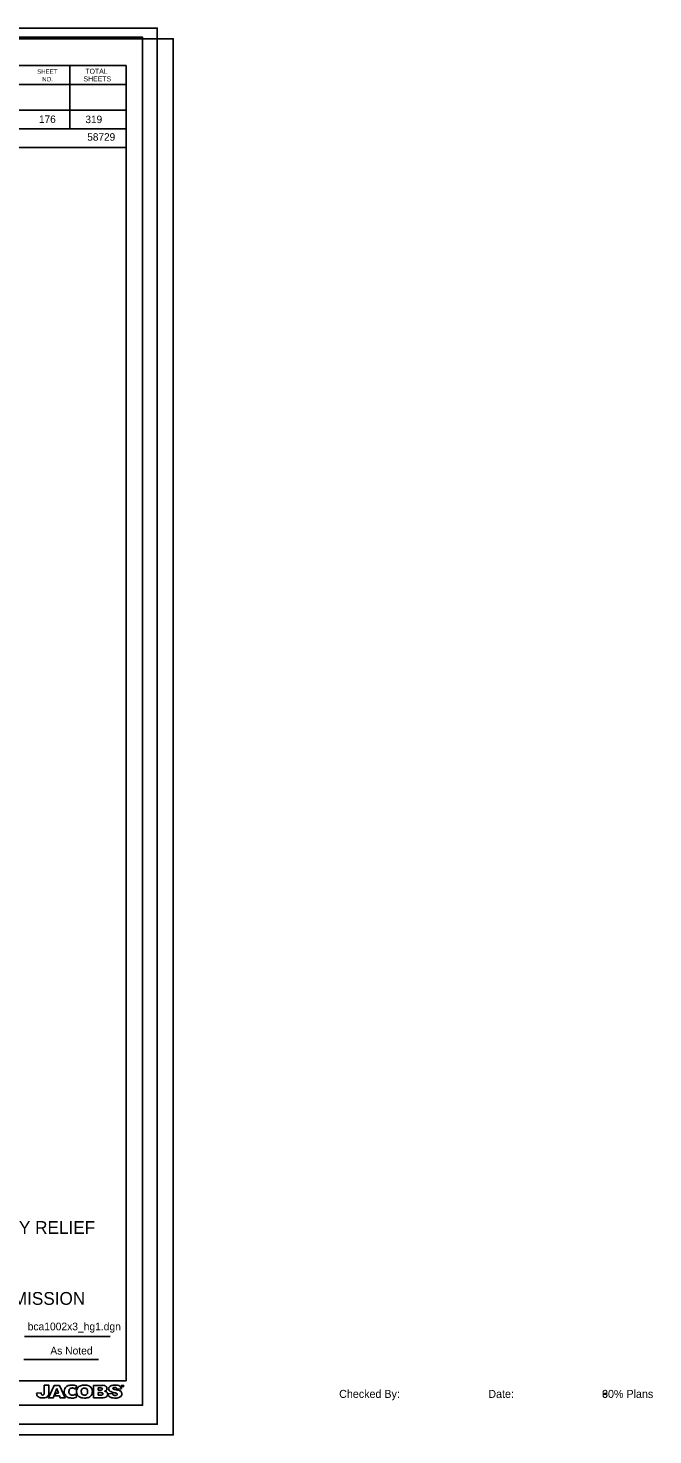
# Model space of a CAD drawing. Extents: x -1063117.9 to -1063075.9, y -253323.6 to -253301.6.
# Drawn here: x -1063085.67 to -1063075.92, y -253323.61 to -253301.63 of the extents above; entities that cross this region are included whole.
import ezdxf

# ---------------------------------------------------------------- set-up
doc = ezdxf.new("R2010")
doc.units = 0
for name, color, linetype in [('30% Plans', 7, 'Continuous'), ('60% Plans', 7, 'Continuous'), ('90% Plans', 7, 'Continuous'), ('border', 7, 'Continuous'), ('Border 2660-Hwy18 - Level 62', 7, 'Continuous'), ('Border 2660-Hwy18 - Level 63', 7, 'Continuous'), ('Border 2660-Hwy18 - Text', 7, 'Continuous'), ('Border 2660-Hwy18 - Title Text', 7, 'Continuous'), ('Level 62 PDF', 7, 'Continuous'), ('Text', 7, 'Continuous'), ('Title Block Text', 7, 'Continuous'), ('Title Text', 7, 'Continuous')]:
    doc.layers.add(name, color=color, linetype=linetype)

msp = doc.modelspace()

# ---------------------------------------------------------------- linework, layer by layer
at = {"layer": 'border'}
for p, q in [((-1063116.157, -253302.216), (-1063084.146, -253302.216)), ((-1063085.026, -253302.216), (-1063085.026, -253303.204)), ((-1063084.146, -253322.761), (-1063084.146, -253302.216)), ((-1063084.146, -253302.51), (-1063088.456, -253302.51)), ((-1063084.146, -253302.508), (-1063084.146, -253302.508)), ((-1063084.146, -253302.91), (-1063088.456, -253302.91)), ((-1063088.16, -253302.91), (-1063084.146, -253302.91)), ((-1063084.146, -253303.204), (-1063092.372, -253303.204)), ((-1063088.456, -253303.495), (-1063084.146, -253303.495)), ((-1063085.73, -253322.071), (-1063084.394, -253322.071)), ((-1063085.742, -253322.431), (-1063084.577, -253322.431)), ((-1063084.146, -253322.761), (-1063116.157, -253322.761))]:
    msp.add_line(p, q, dxfattribs=at)
for points in [[(-1063085.351, -253322.941), (-1063085.351, -253322.831), (-1063085.425, -253322.831), (-1063085.425, -253322.951)], [(-1063085.228, -253322.883), (-1063085.202, -253322.954), (-1063085.241, -253322.954), (-1063085.257, -253322.996), (-1063085.187, -253322.996), (-1063085.175, -253323.029), (-1063085.098, -253323.029), (-1063085.187, -253322.833), (-1063085.268, -253322.833), (-1063085.358, -253323.029), (-1063085.282, -253323.029), (-1063085.228, -253322.883)], [(-1063084.512, -253322.833), (-1063084.654, -253322.833), (-1063084.654, -253323.029)], [(-1063084.547, -253322.872), (-1063084.58, -253322.872), (-1063084.58, -253322.909)], [(-1063084.207, -253322.835), (-1063084.222, -253322.835), (-1063084.222, -253322.837), (-1063084.216, -253322.837), (-1063084.216, -253322.854), (-1063084.214, -253322.854), (-1063084.214, -253322.837), (-1063084.207, -253322.837), (-1063084.207, -253322.835)], [(-1063084.203, -253322.838), (-1063084.203, -253322.838), (-1063084.197, -253322.854), (-1063084.195, -253322.854), (-1063084.189, -253322.838), (-1063084.189, -253322.838), (-1063084.189, -253322.854), (-1063084.186, -253322.854), (-1063084.186, -253322.835), (-1063084.19, -253322.835), (-1063084.196, -253322.851), (-1063084.202, -253322.835), (-1063084.205, -253322.835), (-1063084.205, -253322.854), (-1063084.203, -253322.854), (-1063084.203, -253322.838)], [(-1063085.473, -253322.952), (-1063085.543, -253322.956)], [(-1063084.654, -253323.029), (-1063084.526, -253323.029)], [(-1063084.58, -253322.909), (-1063084.545, -253322.909)], [(-1063084.542, -253322.947), (-1063084.58, -253322.947), (-1063084.58, -253322.987)], [(-1063084.58, -253322.987), (-1063084.542, -253322.987)], [(-1063084.358, -253322.96), (-1063084.428, -253322.964)], [(-1063084.289, -253322.891), (-1063084.219, -253322.888)]]:
    msp.add_lwpolyline(points, dxfattribs=at)
for centre, radius, start, end in [((-1063085.013, -253322.926), 0.0987, 155.2444, 178.6811), ((-1063085.029, -253322.918), 0.0809, 126.8513, 155.2444), ((-1063085.009, -253322.944), 0.114, 94.7853, 126.8513), ((-1063084.988, -253322.93), 0.0556, 110.7655, 134.3139), ((-1063084.989, -253323.193), 0.363, 86.903, 94.7853), ((-1063084.989, -253322.928), 0.0529, 91.5073, 110.7655), ((-1063084.987, -253322.99), 0.116, 82.6359, 91.5073), ((-1063084.979, -253322.924), 0.0493, 65.5548, 82.6359), ((-1063084.975, -253322.943), 0.113, 56.9246, 86.903), ((-1063085.007, -253322.988), 0.119, 54.6002, 65.5548), ((-1063084.689, -253323.008), 0.276, 144.635, 154.8844), ((-1063084.82, -253322.928), 0.1, 148.6249, 181.2859), ((-1063084.841, -253322.915), 0.0755, 123.8806, 148.6249), ((-1063084.804, -253322.971), 0.142, 111.7104, 123.8806), ((-1063084.816, -253322.94), 0.109, 96.5371, 111.7104), ((-1063084.798, -253322.926), 0.0518, 117.7176, 136.1177), ((-1063084.785, -253323.213), 0.384, 91.9058, 96.5371), ((-1063084.804, -253322.914), 0.0382, 100.2108, 117.7176), ((-1063084.795, -253322.965), 0.0895, 90.9675, 100.2108), ((-1063084.791, -253322.995), 0.166, 73.4477, 92.4253), ((-1063084.796, -253322.937), 0.0622, 67.077, 90.4218), ((-1063084.787, -253322.916), 0.0386, 24.6274, 67.077), ((-1063084.775, -253322.943), 0.112, 41.1934, 73.4477), ((-1063084.735, -253322.908), 0.0579, 18.6966, 41.1934), ((-1063084.549, -253323.007), 0.135, 86.2098, 89.3498), ((-1063084.543, -253322.924), 0.0514, 74.8723, 86.2098), ((-1063084.535, -253322.893), 0.0196, 40.2425, 74.8723), ((-1063084.528, -253322.887), 0.0108, 21.9604, 40.2425), ((-1063084.536, -253322.891), 0.0195, 341.4625, 21.9604), ((-1063084.512, -253322.936), 0.104, 72.1885, 90.1477), ((-1063084.499, -253322.895), 0.0603, 61.4844, 72.1885), ((-1063084.497, -253322.892), 0.0564, 34.7868, 61.4844), ((-1063084.476, -253322.877), 0.0315, 16.9455, 34.7868), ((-1063084.49, -253322.881), 0.0455, 347.0949, 16.9455), ((-1063084.372, -253322.888), 0.0476, 124.08, 177.6485), ((-1063084.378, -253322.887), 0.0416, 177.6485, 218.8535), ((-1063084.341, -253322.934), 0.103, 108.2808, 124.08), ((-1063084.347, -253322.913), 0.0811, 99.8173, 108.2808), ((-1063084.32, -253323.072), 0.242, 93.402, 99.8173), ((-1063084.335, -253322.883), 0.016, 146.4706, 165.3108), ((-1063084.343, -253322.881), 0.00815, 165.3108, 208.2887), ((-1063084.336, -253322.876), 0.0169, 211.7417, 226.6339), ((-1063084.341, -253322.879), 0.00877, 130.7855, 146.4706), ((-1063084.331, -253322.892), 0.0256, 97.3055, 130.7855), ((-1063084.319, -253323.083), 0.254, 80.6549, 93.402), ((-1063084.325, -253322.935), 0.0692, 81.3212, 97.3055), ((-1063084.32, -253322.902), 0.0359, 57.474, 81.3212), ((-1063084.312, -253322.889), 0.0202, 37.1977, 57.474), ((-1063084.323, -253322.898), 0.0351, 11.0051, 37.1977), ((-1063084.293, -253322.921), 0.0897, 57.5906, 80.6549), ((-1063084.271, -253322.887), 0.0494, 39.0736, 57.5906), ((-1063084.28, -253322.895), 0.0612, 6.4385, 39.0736), ((-1063085.421, -253322.946), 0.123, 184.5698, 198.1069), ((-1063085.488, -253322.968), 0.0527, 198.1069, 225.9799), ((-1063085.469, -253322.949), 0.0797, 225.9799, 261.0714), ((-1063085.444, -253322.786), 0.244, 261.0714, 269.9405), ((-1063085.412, -253322.954), 0.0602, 178.2556, 191.4961), ((-1063085.444, -253322.961), 0.0277, 191.4961, 218.7511), ((-1063085.453, -253322.968), 0.0164, 218.7511, 257.488), ((-1063085.449, -253322.95), 0.0345, 257.488, 275.7834), ((-1063085.448, -253322.959), 0.0257, 275.7834, 301.6926), ((-1063085.444, -253322.863), 0.167, 269.9405, 279.1616), ((-1063085.441, -253322.97), 0.0122, 301.6926, 325.4171), ((-1063085.455, -253322.961), 0.0285, 325.4171, 349.1575), ((-1063085.504, -253322.952), 0.0792, 349.1575, 360), ((-1063085.432, -253322.936), 0.0931, 279.1616, 305.8646), ((-1063085.412, -253322.964), 0.0585, 305.8646, 338.7843), ((-1063085.406, -253322.966), 0.0527, 338.7843, 350.0951), ((-1063085.895, -253322.881), 0.549, 350.0951, 351.3706), ((-1063085.475, -253322.945), 0.124, 351.3706, 1.8291), ((-1063084.959, -253322.927), 0.153, 178.6811, 194.3912), ((-1063085.05, -253322.95), 0.0582, 194.3912, 214.1799), ((-1063084.994, -253322.912), 0.127, 214.1799, 231.6615), ((-1063085.025, -253322.951), 0.0765, 231.6616, 258.686), ((-1063084.981, -253322.734), 0.298, 258.686, 268.8163), ((-1063084.934, -253322.933), 0.104, 161.2834, 178.6702), ((-1063084.953, -253322.933), 0.0855, 178.6702, 195.8531), ((-1063084.994, -253322.945), 0.0421, 195.8531, 214.5369), ((-1063085.01, -253322.908), 0.0243, 134.3139, 161.2834), ((-1063084.997, -253322.946), 0.0388, 214.5369, 253.1918), ((-1063084.986, -253322.91), 0.0769, 253.1918, 291.1956), ((-1063084.985, -253322.886), 0.146, 268.8163, 299.3878), ((-1063084.992, -253322.895), 0.0928, 291.1956, 305.5144), ((-1063084.575, -253322.788), 0.407, 206.7197, 213.678), ((-1063084.768, -253322.927), 0.152, 181.2859, 193.1956), ((-1063084.85, -253322.946), 0.0683, 193.1956, 217.7499), ((-1063084.816, -253322.92), 0.111, 217.7499, 244.1703), ((-1063084.827, -253322.943), 0.0859, 244.1703, 259.4942), ((-1063084.755, -253322.931), 0.0917, 160.8611, 181.2981), ((-1063084.751, -253322.931), 0.0951, 181.2981, 197.9492), ((-1063084.788, -253322.733), 0.299, 259.4942, 268.6426), ((-1063084.814, -253322.91), 0.0287, 136.1177, 160.8611), ((-1063084.814, -253322.951), 0.0299, 197.9492, 222.7741), ((-1063084.801, -253322.939), 0.0474, 222.7741, 250.1955), ((-1063084.8, -253322.936), 0.0507, 250.1955, 269.1264), ((-1063084.797, -253322.795), 0.191, 269.1264, 272.0424), ((-1063084.791, -253322.852), 0.18, 268.6426, 285.9017), ((-1063084.792, -253322.935), 0.0512, 272.0424, 299.5401), ((-1063084.785, -253322.949), 0.036, 299.5401, 342.4003), ((-1063084.803, -253322.923), 0.056, 2.7442, 24.6274), ((-1063084.837, -253322.932), 0.091, 342.4003, 0.0845), ((-1063084.996, -253322.932), 0.249, 0.0845, 2.7442), ((-1063084.769, -253322.929), 0.101, 285.9017, 322.6714), ((-1063084.745, -253322.947), 0.0698, 322.6714, 344.5708), ((-1063084.803, -253322.931), 0.13, 344.5708, 18.6966), ((-1063084.545, -253322.846), 0.0633, 270.0363, 284.1438), ((-1063084.547, -253323.194), 0.247, 86.6838, 88.8756), ((-1063084.542, -253322.883), 0.104, 270.0001, 276.6749), ((-1063084.536, -253322.997), 0.0497, 75.9314, 86.6838), ((-1063084.535, -253322.888), 0.0196, 284.1438, 307.8865), ((-1063084.535, -253322.943), 0.043, 276.6749, 293.0645), ((-1063084.537, -253322.691), 0.338, 271.7224, 279.6279), ((-1063084.532, -253322.892), 0.0149, 307.8866, 341.4625), ((-1063084.531, -253322.98), 0.0328, 59.6202, 75.9314), ((-1063084.525, -253322.966), 0.0178, 293.0645, 337.5037), ((-1063084.522, -253322.965), 0.015, 30.8341, 59.6202), ((-1063084.525, -253322.966), 0.0177, 337.5037, 30.8341), ((-1063084.502, -253322.851), 0.0753, 284.6785, 296.8411), ((-1063084.499, -253323.015), 0.092, 61.0815, 79.9242), ((-1063084.49, -253322.964), 0.0609, 279.6279, 313.6357), ((-1063084.489, -253322.877), 0.0471, 296.8412, 329.8182), ((-1063084.474, -253322.968), 0.039, 44.9773, 61.0815), ((-1063084.475, -253322.885), 0.0307, 329.8182, 347.0949), ((-1063084.484, -253322.971), 0.0511, 313.6357, 342.9845), ((-1063084.478, -253322.973), 0.0452, 342.9845, 44.9773), ((-1063084.052, -253322.911), 0.38, 187.9971, 189.0947), ((-1063084.378, -253322.963), 0.0503, 189.0947, 202.464), ((-1063084.343, -253322.949), 0.0881, 202.464, 215.8926), ((-1063084.364, -253322.964), 0.0621, 215.8926, 243.2968), ((-1063084.366, -253322.878), 0.0566, 218.8535, 233.6549), ((-1063084.352, -253322.859), 0.0797, 233.6549, 244.7689), ((-1063084.351, -253322.939), 0.0904, 243.2968, 257.4598), ((-1063084.32, -253322.79), 0.156, 244.7689, 253.473), ((-1063084.324, -253322.819), 0.213, 257.4598, 268.8656), ((-1063084.272, -253322.63), 0.323, 253.473, 259.8297), ((-1063084.306, -253322.952), 0.0523, 188.5141, 201.638), ((-1063084.325, -253322.96), 0.0319, 201.638, 242.3635), ((-1063084.338, -253322.878), 0.0145, 226.6339, 245.1429), ((-1063084.321, -253322.841), 0.0549, 245.1429, 260.9806), ((-1063084.319, -253322.948), 0.045, 242.3635, 264.6229), ((-1063084.404, -253323.369), 0.479, 77.5139, 80.9806), ((-1063084.382, -253323.24), 0.297, 76.0104, 79.8297), ((-1063084.317, -253322.451), 0.581, 268.8656, 270.7612), ((-1063084.316, -253322.913), 0.0806, 264.6229, 273.901), ((-1063084.334, -253323.047), 0.0974, 67.9593, 76.0104), ((-1063084.314, -253322.947), 0.0464, 273.901, 289.1925), ((-1063084.312, -253322.855), 0.177, 270.7612, 282.5001), ((-1063084.728, -253324.831), 1.977, 76.8035, 77.5139), ((-1063084.307, -253322.966), 0.0263, 289.1925, 322.566), ((-1063084.307, -253322.981), 0.0265, 39.9313, 67.9593), ((-1063084.298, -253322.973), 0.0145, 2.1813, 39.9313), ((-1063084.297, -253322.973), 0.0141, 322.566, 2.1813), ((-1063084.314, -253323.065), 0.163, 65.6998, 76.8035), ((-1063084.297, -253322.921), 0.109, 282.5001, 295.6144), ((-1063084.283, -253322.95), 0.0772, 295.6144, 314.022), ((-1063084.279, -253322.987), 0.0776, 51.3565, 65.6998), ((-1063084.263, -253322.967), 0.0523, 36.5162, 51.3565), ((-1063084.272, -253322.962), 0.0608, 314.022, 345.1611), ((-1063084.26, -253322.965), 0.0486, 345.1611, 36.5162)]:
    msp.add_arc(centre, radius, start, end, dxfattribs=at)
at = {"layer": 'Border 2660-Hwy18 - Level 62'}
msp.add_lwpolyline([(-1063117.777, -253301.63), (-1063083.659, -253301.63), (-1063083.659, -253323.44), (-1063117.777, -253323.44)], close=True, dxfattribs=at)
at = {"layer": 'Border 2660-Hwy18 - Level 63'}
msp.add_lwpolyline([(-1063117.888, -253301.773), (-1063083.889, -253301.773), (-1063083.889, -253323.143), (-1063117.888, -253323.143)], close=True, dxfattribs=at)
at = {"layer": 'Level 62 PDF'}
msp.add_lwpolyline([(-1063117.527, -253301.797), (-1063083.409, -253301.797), (-1063083.409, -253323.607), (-1063117.527, -253323.607)], close=True, dxfattribs=at)

# ---------------------------------------------------------------- texts
at = {"layer": '30% Plans'}
for s, p in [('Checked By:', (-1063080.82, -253323.029)), ('Date:', (-1063078.491, -253323.029)), ('30% Plans', (-1063076.716, -253323.029))]:
    msp.add_text(s, height=0.125, dxfattribs=at).set_placement(p)
at = {"layer": '60% Plans'}
for s, p in [('Checked By:', (-1063080.82, -253323.029)), ('Date:', (-1063078.491, -253323.029)), ('60% Plans', (-1063076.716, -253323.029))]:
    msp.add_text(s, height=0.125, dxfattribs=at).set_placement(p)
at = {"layer": '90% Plans'}
for s, p in [('Checked By:', (-1063080.82, -253323.029)), ('Date:', (-1063078.491, -253323.029)), ('90% Plans', (-1063076.716, -253323.029))]:
    msp.add_text(s, height=0.125, dxfattribs=at).set_placement(p)
at = {"layer": 'Border 2660-Hwy18 - Text'}
for s, height, p in [('SHEET', 0.0684, (-1063085.534, -253302.343)), ('NO.', 0.0684, (-1063085.456, -253302.462)), ('SHEETS', 0.0782, (-1063084.811, -253302.462)), ('TOTAL', 0.0782, (-1063084.782, -253302.343)), ('319', 0.1172, (-1063084.781, -253303.114))]:
    msp.add_text(s, height=height, dxfattribs=at).set_placement(p)
at = {"layer": 'Border 2660-Hwy18 - Title Text'}
msp.add_text('ARKANSAS STATE HIGHWAY COMMISSION', height=0.2, dxfattribs=at).set_placement((-1063090.357, -253321.575))
at = {"layer": 'Text'}
for s, height, p in [('176', 0.1172, (-1063085.506, -253303.112)), ('As Noted', 0.12, (-1063085.329, -253322.351))]:
    msp.add_text(s, height=height, dxfattribs=at).set_placement(p)
at = {"layer": 'Title Block Text'}
msp.add_text('bca1002x3_hg1.dgn', height=0.12, dxfattribs=at).set_placement((-1063085.682, -253321.973))
at = {"layer": 'Title Text'}
for s, height, p in [('58729', 0.1172, (-1063084.752, -253303.389)), ('HYDROGRAPH - BIG LAKE FLOODWAY RELIEF', 0.2, (-1063090.619, -253320.467))]:
    msp.add_text(s, height=height, dxfattribs=at).set_placement(p)

doc.saveas('drawing.dxf')
